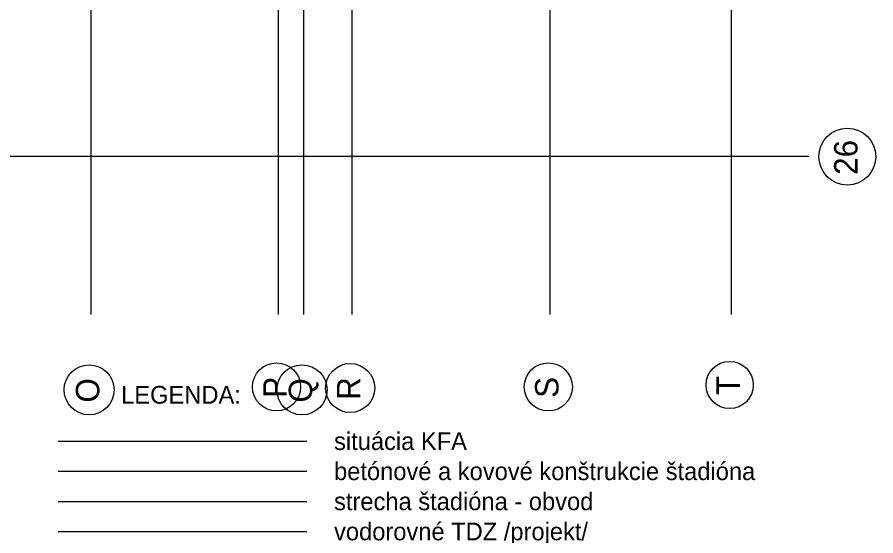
# Model space of a CAD drawing. Extents: x -264205 to -263659, y -1242401 to -1242060.
# Drawn here: x -263822.21 to -263790.15, y -1242254.98 to -1242235.6 of the extents above; entities that cross this region are included whole.
import ezdxf

# ---------------------------------------------------------------- set-up
doc = ezdxf.new("R2010")
doc.units = 0
doc.layers.add('LEGENDA', color=7, linetype='Continuous')
doc.layers.add('OSI_STAVBY_KFA', color=7, linetype='Continuous')

msp = doc.modelspace()

# ---------------------------------------------------------------- linework, layer by layer
at = {"layer": 'LEGENDA'}
for p, q in [((-263820.678, -1242251.443), (-263811.395, -1242251.443)), ((-263820.678, -1242252.568), (-263811.395, -1242252.568)), ((-263820.678, -1242253.693), (-263811.395, -1242253.693)), ((-263820.678, -1242254.818), (-263811.395, -1242254.818))]:
    msp.add_line(p, q, dxfattribs=at)
at = {"layer": 'OSI_STAVBY_KFA'}
for p, q in [((-263819.468, -1242083.237), (-263819.468, -1242246.707)), ((-263812.468, -1242083.237), (-263812.468, -1242246.707)), ((-263811.518, -1242083.237), (-263811.518, -1242246.707)), ((-263809.718, -1242083.237), (-263809.718, -1242246.707)), ((-263802.318, -1242083.237), (-263802.318, -1242246.707)), ((-263795.543, -1242083.237), (-263795.543, -1242246.707)), ((-263792.653, -1242240.807), (-263911.523, -1242240.807)), ((-263792.653, -1242240.807), (-263792.653, -1242240.807))]:
    msp.add_line(p, q, dxfattribs=at)
for centre, radius in [((-263791.21, -1242240.807), 1.064), ((-263819.528, -1242249.526), 0.935), ((-263812.528, -1242249.416), 0.899), ((-263811.578, -1242249.526), 0.935), ((-263809.778, -1242249.457), 0.916), ((-263802.378, -1242249.416), 0.899), ((-263795.603, -1242249.345), 0.882)]:
    msp.add_circle(centre, radius, dxfattribs=at)

# ---------------------------------------------------------------- texts
at = {"layer": 'LEGENDA'}
for s, height, p in [('LEGENDA:', 0.6613, (-263818.332, -1242250.041)), ('situácia KFA', 0.66129, (-263810.38, -1242251.774)), ('betónové a kovové konštrukcie štadióna', 0.66129, (-263810.38, -1242252.899)), ('strecha štadióna - obvod', 0.66129, (-263810.38, -1242254.024)), ('vodorovné TDZ /projekt/', 0.66129, (-263810.38, -1242255.149))]:
    msp.add_text(s, height=height, dxfattribs=at).set_placement(p)
at = {"layer": 'OSI_STAVBY_KFA'}
for s, p in [('26', (-263790.829, -1242241.487)), ('T', (-263795.222, -1242249.718)), ('O', (-263819.147, -1242250.001)), ('P', (-263812.147, -1242249.824)), ('Q', (-263811.197, -1242250.001)), ('R', (-263809.397, -1242249.898)), ('S', (-263801.997, -1242249.824))]:
    msp.add_text(s, height=0.875, rotation=90, dxfattribs=at).set_placement(p)

doc.saveas('drawing.dxf')
